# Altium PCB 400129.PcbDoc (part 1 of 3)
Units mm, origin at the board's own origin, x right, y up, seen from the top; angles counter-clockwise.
Board outline 295.85 x 54.86 mm, 2 copper layers (Top Layer, Bottom Layer), stack 1.671 mm thick; 222 components, 127 nets, 693 pads, 1827 vias.
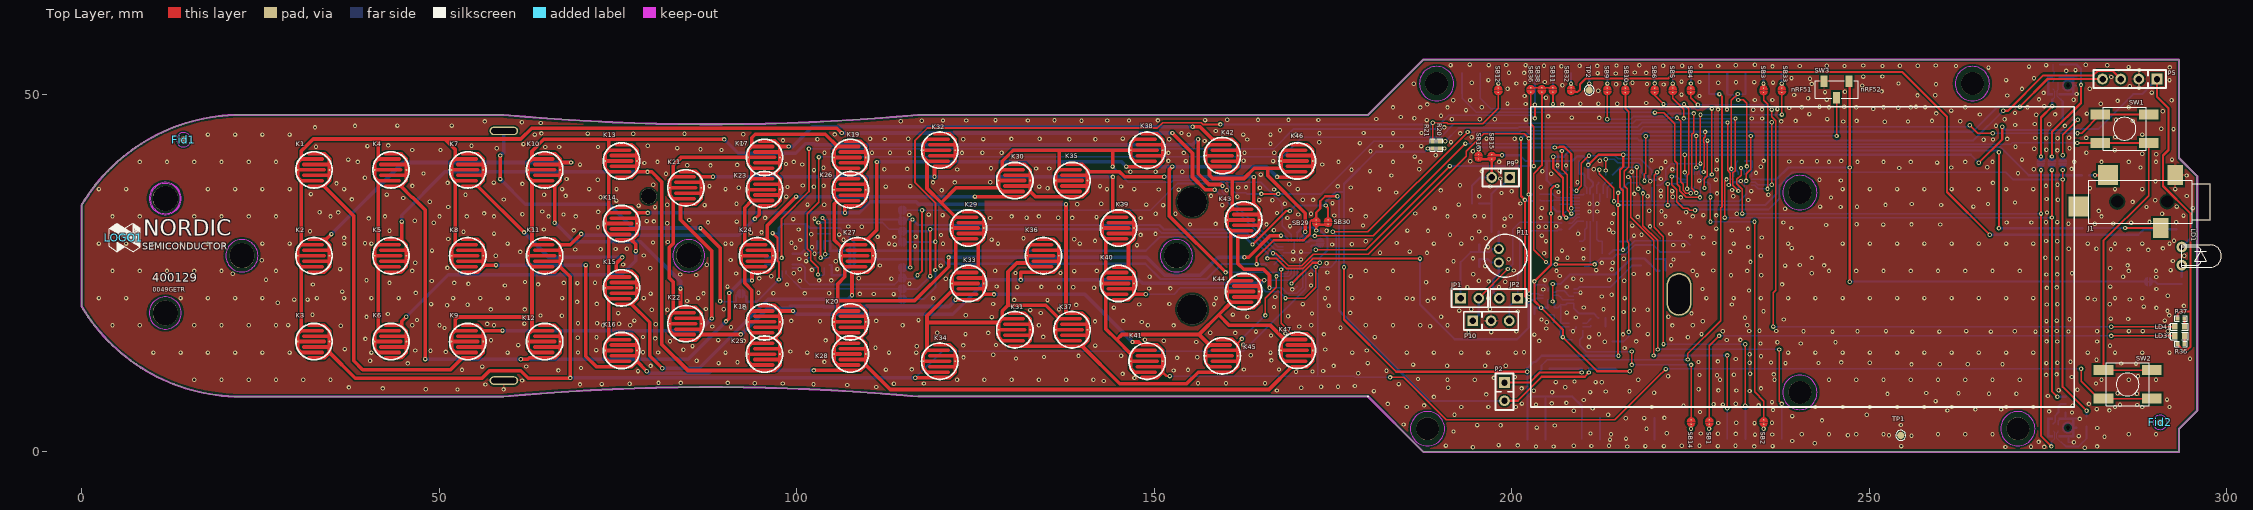
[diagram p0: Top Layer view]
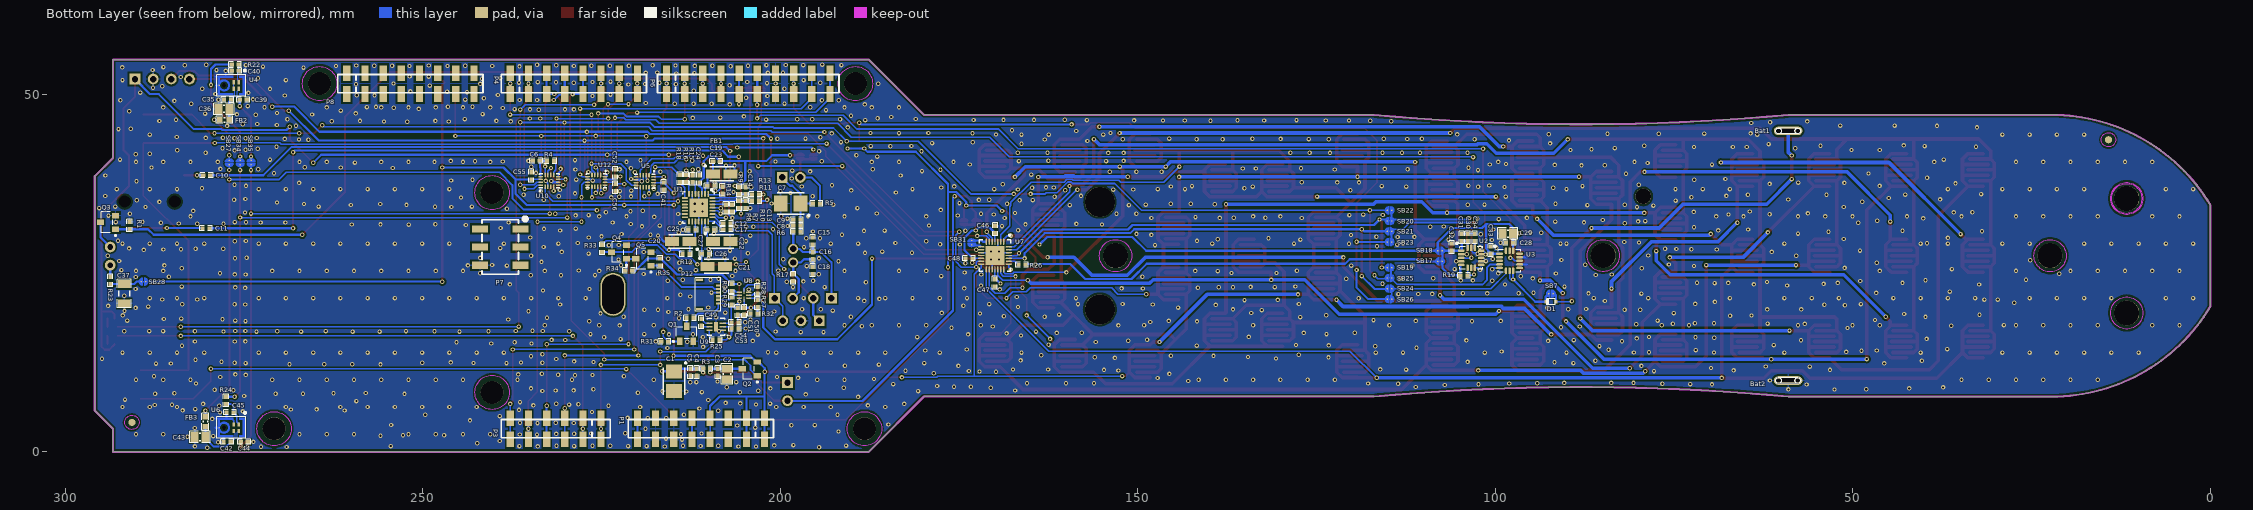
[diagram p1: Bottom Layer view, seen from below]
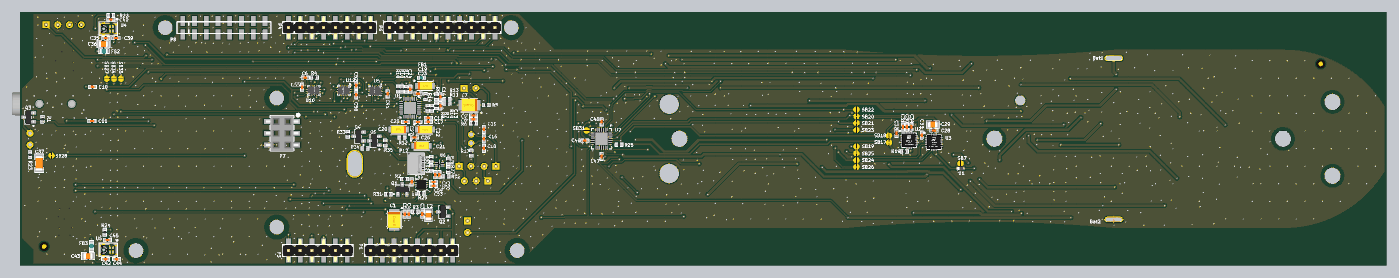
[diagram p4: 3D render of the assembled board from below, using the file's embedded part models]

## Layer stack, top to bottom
Top Solder: solder mask 0.0102, Solder Resist, Dk 3.5
Top Layer: signal copper 0.0356
Dielectric1: core 1.6, FR-4, Dk 4.8
Bottom Layer: signal copper 0.0356
Bottom Solder: solder mask 0.0102, Solder Resist, Dk 3.5

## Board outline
22.2,7.732 59,7.732 cw(c88,-308.964) 117,7.732 116.999,7.748 179.876,7.748 187.624,0 293.3,0 293.3,3.243 295.84,5.783 295.84,38.549 293.3,41.089 293.3,54.864 187.624,54.864 179.892,47.132 117,47.132 cw(c88,363.828) 59,47.132 22.2,47.132 ccw(c22.215,21.249) 0,34.532 0,20.332 -0.01,20.349 ccw(c22.2,33.589)

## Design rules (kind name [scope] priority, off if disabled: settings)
Clearance ANT_Clerance [InNet('ANT')] p1: gap=0.127
Clearance Polygon_Clearance [(InNamedPolygon('Top_Layer-GND')) or (InNamedPolygon('Bottom_Layer-GND'))] p2: gap=0.254
Clearance [All] p3: gap=0.127
ComponentClearance [All] p1 off: gap=0.254 collisioncheckmode=3 verticalgap=0.254 showdistances=FALSE
DiffPairsRouting [All] p1: maxlimit=0.15 minlimit=0.15 mostfreqgap=0.15 toplayer_minwidth=0.381 toplayer_maxwidth=0.381 toplayer_prefwidth=0.381 bottomlayer_minwidth=0.381 bottomlayer_maxwidth=0.381 bottomlayer_prefwidth=0.381 maxuncoupledlength=12.7
FabricationTestPointUsage TestPointUsage [All] p1: valid=0 allowmultiple=FALSE
FabricationTestpoint Testpoint [All] p1: side=3 testpointundercomponent=TRUE minsize=1.016 maxsize=2.54 preferedsize=1.524 minholesize=0 maxholesize=1.016 preferedholesize=0.813 testpointgrid=0.025 allowsidetop=TRUE allowsidebottom=TRUE usegrid=TRUE gridtolerance=0
Height [All] p1 off: minheight=0 maxheight=25.4 prefheight=12.7
HoleSize [All] p1: absolutevalues=TRUE maxlimit=6.35 minlimit=0.3 maxpercent=80.000 minpercent=20.000
MinimumAnnularRing [All] p1 off: minimumring=0.152
PolygonConnect PolygonConnect_1 [isVia and innet(gnd)] p1: connectstyle=Direct reliefconductorwidth=0.254 reliefentries=4 polygonreliefangle="90 Angle" airgapwidth=0.254
PolygonConnect [All] p2: connectstyle=Relief reliefconductorwidth=0.254 reliefentries=4 polygonreliefangle="90 Angle" airgapwidth=0.254
RoutingVias [All] p1: holewidth=0.305 width=0.61 viastyle="Through Hole" minholewidth=0.3 minwidth=0.6 maxholewidth=0.711 maxwidth=1.27
SilkToSolderMaskClearance SilkscreenOverComponentPads [IsPad] p1: minsilkscreentomaskgap=0.254 clearancetoexposedcopper=TRUE
SolderMaskExpansion [All] p1: expansion=0.076
Width [All] p1: maxlimit=2.54 minlimit=0.152 preferedwidth=0.152
23 further rules are at their usual default settings.

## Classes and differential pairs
component class "pca63519 - Power": Bat1 Bat2 C1 C2 C3 C4 C5 D1 P2 Q2 R3 SB7
component class "pca63519 - Codec": C7 C8 C9 C10 C11 C12 C13 C14 C15 C16 C17 C18 C19 C20 C21 C22 C23 C24 C25 C26 C27 FB1 J1 JP1 JP2 P9 P10 P11 R5 R6 R7 R8 R9 R10 R11 R12 R13 R14 R15 R16 R17 R18 SB15 SB16 U1
component class "pca63519 - Connectors": C6 C41 C52 C55 C56 Fid1 Fid2 LD3 LD4 LOGO1 P1 P3 P4 P5 P6 P7 P8 R4 R36 R37 SB1 SB2 SB3 SB4 SB5 SB6 SB9 SB10 SB11 SB12 SB14 SB32 SB33 SW3 TP1 TP2 U5 U10 U12
component class "pca63519 - Keyboard": C46 C47 C48 K1 K2 K3 K4 K5 K6 K7 K8 K9 K10 K11 K12 K13 K14 K15 K16 K17 K18 K19 K20 K21 K22 K23 K24 K25 K26 K27 K28 K29 K30 K31 K32 K33 K34 K35 K36 K37 K38 K39 K40 K41 K42 K43 K44 K45 K46 K47 R26 SB29 SB30 SB31 SB36 SW1 SW2 U7
component class "pca63519 - Sensors": C28 C29 C30 C31 C32 C33 C34 C35 C36 C37 C39 C40 C42 C43 C44 C45 FB2 FB3 LD1 Q3 R1 R19 R20 R21 R22 R23 R24 SB17 SB18 SB19 SB20 SB21 SB22 SB23 SB24 SB25 SB26 SB27 SB28 SB34 SB35 U2 U3 U4 U6
component class "pca63519 - TouchPad": C49 C50 C51 C53 C54 P12 Q1 Q4 Q5 R2 R25 R27 R28 R29 R30 R31 R32 R33 R34 R35 SB38 U8 U9

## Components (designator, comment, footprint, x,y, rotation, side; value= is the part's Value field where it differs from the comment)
Bat1 "AA" POLSATBATTERYHOLDER 59.05,44.882 r0 bottom
Bat2 "AA" POLSATBATTERYHOLDER 59.05,9.982 r0 bottom
C1 "100µF" CAPMP3528X21N 214.838,9.891 r270 bottom
C2 "22µF" CAPC2012X11L 207.438,10.887 r90 bottom
C3 "100nF" CAPC1005X04L 208.743,11.135 r90 bottom
C4 "100nF" CAPC1005X04L 211.693,11.131 r90 bottom
C5 "1.0µF" CAPC1005X04L 212.579,11.131 r90 bottom
C6 "33pF" CAPC1005X04L 234.098,40.695 r180 bottom
C7 "100µF" CAPMP3528X21N 198.541,34.726 r0 bottom
C8 "100nF" CAPC1005X04L 197.657,31.658 r180 bottom
C9 "1.0µF" CAPC1005X04L 197.657,32.493 r180 bottom
C10 "1.0µF" CAPC1005X04L 280.193,38.689 r180 bottom
C11 "1.0µF" CAPC1005X04L 280.286,31.281 r180 bottom
C12 "1.0µF" CAPC1005X04L 207.458,31.996 r0 bottom
C13 "N.C." CAPC1005X04L 204.832,34.589 r90 bottom
C14 "N.C." CAPC1005X04L 204.832,36.525 r270 bottom
C15 "10nF" CAPC1005X04L 195.452,29.486 r270 bottom
C16 "N.C." CAPC1005X04L 195.451,27.434 r90 bottom
C17 "1.0µF" CAPC1005X04L 207.458,31.121 r0 bottom
C18 "N.C." CAPC1005X04L 195.449,25.382 r90 bottom
C19 "10µF" CAPMP3216X18N 208.166,38.891 r180 bottom
C20 "10µF" CAPMP3216X18N 213.889,29.433 r0 bottom
C21 "10µF" CAPMP3216X18N 208.92,25.957 r180 bottom
C22 "10µF" CAPMP3216X18N 208.185,29.433 r180 bottom
C23 "100nF" CAPC1005X04L 209.687,37.234 r0 bottom
C24 "100nF" CAPC1005X04L 211.343,38.185 r270 bottom
C25 "100nF" CAPC1005X04L 212.353,31.083 r180 bottom
C26 "100nF" CAPC1005X04L 210.447,27.734 r0 bottom
C27 "100nF" CAPC1005X04L 209.712,31.083 r0 bottom
C28 "100nF" CAPC1005X04L 97.999,29.239 r180 bottom
C29 "10µF" CAPC2012X11L 98.246,30.529 r180 bottom
C30 "100nF" CAPC1005X04L 103.851,29.985 r270 bottom
C31 "2.2µF" CAPC1005X04L 104.697,29.983 r270 bottom
C32 "10nF" CAPC1005X04L 106.096,28.631 r270 bottom
C33 "100nF" CAPC1005X04L 100.623,28.219 r270 bottom
C34 "470nF" CAPC1005X04L 102.856,29.985 r270 bottom
C35 "10nF" CAPC1005X04L 277.278,49.264 r180 bottom
C36 "10µF" CAPC2012X11L 277.785,47.969 r180 bottom
C37 "100µF" CAPC3216X13L 291.719,22.134 r90 bottom
C39 "15pF" CAPC1005X04L 275.09,49.268 r0 bottom
C40 "15pF" CAPC1005X04L 276.201,53.285 r180 bottom
C41 "100nF" CAPC1005X04L 216.286,37.171 r90 bottom
C42 "10nF" CAPC1005X04L 277.338,1.388 r180 bottom
C43 "10µF" CAPC2012X11L 281.123,2.08 r180 bottom
C44 "15pF" CAPC1005X04L 274.949,1.388 r0 bottom
C45 "15pF" CAPC1005X04L 276.938,5.533 r180 bottom
C46 "100nF" CAPC1005X04L 169.953,31.112 r270 bottom
C47 "100nF" CAPC1005X04L 169.96,23.629 r90 bottom
C48 "100nF" CAPC1005X04L 173.583,27.064 r180 bottom
C49 "1.0µF" CAPC1005X04L 211.057,18.122 r270 bottom
C50 "100nF" CAPC1005X04L 205.052,19.663 r90 bottom
C51 "100nF" CAPC1005X04L 205.955,19.663 r90 bottom
C52 "10µF" CAPC1005X04L 223.065,39.005 r270 bottom
C53 "1.0µF" CAPC1005X04L 206.312,17.253 r0 bottom
C54 "4.7µF" CAPC1005X04L 206.312,18.101 r0 bottom
C55 "100nF" CAPC1005X04L 234.789,38.606 r270 bottom
C56 "100nF" CAPC1005X04L 223.065,36.981 r90 bottom
D1 "1PS79SB30.115" SOD-523 92.228,21.008 r180 bottom
FB1 "600R/0.3A" INDC1005X04L 208.921,40.658 r180 bottom
FB2 "600R/0.5A" INDC1608X06L 277.716,46.428 r0 bottom
FB3 "600R/0.5A" INDC1608X06L 280.373,4.235 r90 bottom
Fid1 "Fiducial mark" Fiducial 14.251,43.65 r0 top
Fid2 "Fiducial mark" Fiducial 290.642,4.128 r0 top
J1 "JACK, PHONO" SJ-3523-SMT-TR 291.655,34.996 r180 top
JP1 "Jumper" Jumper-2.54mm 194.105,21.502 r0 top
JP2 "Jumper" Jumper-2.54mm 199.516,21.494 r180 top
K1 "*" "PCB Switch"#1 32.5,39.432 r0 top
K2 "0" "PCB Switch"#1 32.5,27.432 r0 top
K3 "#" "PCB Switch"#1 32.5,15.432 r0 top
K4 "7" "PCB Switch"#1 43.25,39.432 r0 top
K5 "8" "PCB Switch"#1 43.25,27.432 r0 top
K6 "9" "PCB Switch"#1 43.25,15.432 r0 top
K7 "4" "PCB Switch"#1 54,39.432 r0 top
K8 "5" "PCB Switch"#1 54,27.432 r0 top
K9 "6" "PCB Switch"#1 54,15.432 r0 top
K10 "1" "PCB Switch"#2 64.75,39.432 r0 top
K11 "2" "PCB Switch"#1 64.75,27.432 r0 top
K12 "3" "PCB Switch"#1 64.75,15.432 r0 top
K13 "Red" "PCB Switch"#1 75.5,40.682 r0 top
K14 "Green" "PCB Switch"#1 75.5,31.932 r0 top
K15 "Yellow" "PCB Switch"#1 75.5,22.932 r0 top
K16 "Blue" "PCB Switch"#1 75.5,14.182 r0 top
K17 "PCB SW" "PCB Switch"#1 95.5,41.182 r0 top
K18 "PCB SW" "PCB Switch"#1 95.5,18.182 r0 top
K19 "PCB SW" "PCB Switch"#1 107.5,41.177 r0 top
K20 "PCB SW" "PCB Switch"#1 107.5,18.182 r0 top
K21 "TBD" "PCB Switch"#1 84.5,36.932 r0 top
K22 "TBD" "PCB Switch"#1 84.5,17.932 r0 top
K23 "V_Down" "PCB Switch"#1 95.5,36.682 r0 top
K24 "Mute" "PCB Switch"#1 94.5,27.432 r0 top
K25 "C_Down" "PCB Switch"#1 95.5,13.674 r0 top
K26 "V_Up" "PCB Switch"#1 107.5,36.663 r0 top
K27 "Back" "PCB Switch"#1 108.5,27.432 r0 top
K28 "C_Up" "PCB Switch"#1 107.5,13.682 r0 top
K29 "PCB SW" "PCB Switch"#1 124,31.307 r0 top
K30 "PCB SW" "PCB Switch"#1 130.5,37.944 r0 top
K31 "PCB SW" "PCB Switch"#3 130.5,17.083 r0 top
K32 "Menu" "PCB Switch"#1 120,42.193 r0 top
K33 "Down" "PCB Switch"#1 124,23.557 r0 top
K34 "Exit" "PCB Switch"#1 120,12.682 r0 top
K35 "Left" "PCB Switch"#1 138.5,37.944 r0 top
K36 "OK" "PCB Switch"#1 134.5,27.432 r0 top
K37 "Right" "PCB Switch"#1 138.5,17.083 r0 top
K38 "TBD" "PCB Switch"#1 149,42.182 r0 top
K39 "PCB SW" "PCB Switch"#1 145,31.307 r0 top
K40 "Up" "PCB Switch"#4 145,23.557 r0 top
K41 "TBD" "PCB Switch"#1 149,12.682 r0 top
K42 "TV" "PCB Switch"#1 159.5,41.432 r0 top
K43 "SAT" "PCB Switch"#1 162.5,32.432 r0 top
K44 "DVD" "PCB Switch"#1 162.5,22.432 r0 top
K45 "AUX" "PCB Switch"#1 159.5,13.432 r0 top
K46 "Power" "PCB Switch"#1 170,40.682 r0 top
K47 "TBD" "PCB Switch"#1 170,14.194 r0 top
LD1 "IR333C/H2" LED_3MM_SIDE 293.691,27.391 r0 top
LD3 "L0603G" LED_0603_G 293.37,16.219 r0 top
LD4 "L0603G" LED_0603_G 293.37,17.503 r0 top
LOGO1 "Nordic Logo M" NORDIC_LOGO_M 5.86,29.941 r0 top
P1 "Pin List 1x8" LIST_1x8_SMD 202.18,3.243 r0 bottom
P2 "Pin List 1x2" LIST_1x2 198.972,8.421 r270 top
P3 "Pin List 1x6" LIST_1x6_SMD 225.04,3.243 r0 bottom
P4 "Pin List 1x8" LIST_1x8_SMD 237.74,51.503 r180 bottom
P5 "Pin List 1x4" LIST_1x4 286.413,52.14 r180 top
P6 "Pin List 1x10" LIST_1x10_SMD 215.896,51.503 r180 bottom
P7 "Socket 2x3" SOCKET_2x3_SMD-2.54mm-bottom 239.137,28.643 r270 top
P8 "Pin List 1x8" LIST_1x8_SMD 260.6,51.503 r180 bottom
P9 "Pin List 1x2" LIST_1x2 198.452,38.381 r180 top
P10 "Pin List 1x3" LIST_1x3 197.091,18.321 r0 top
P11 "VMOB6027D" MIC_VMOB6027D 199.129,27.432 r0 top
P12 "5034800600" "Molex 5034800600" 210.073,22.025 r270 bottom
Q1 "FDV303N" SOT-23a 214.034,15.457 r180 bottom
Q2 "FDV304P" SOT-23a 203.194,10.674 r90 bottom
Q3 "FDV303N" SOT-23a 292.949,31.148 r90 bottom
Q4 "BC847C" SOT-23a 221.492,26.995 r90 bottom
Q5 "BC847C" SOT-23a 218.076,26.046 r90 bottom
R1 "1M0" RESC1005X04L 291.007,31.664 r270 bottom
R2 "220R" RESC1005X04L 212.6,18.707 r180 bottom
R3 "10R" RESC1005X04L 210.273,11.633 r0 bottom
R4 "33R" RESC1005X04L 232.117,40.695 r0 bottom
R5 "0R" RESC1005X04L 194.939,34.74 r180 bottom
R6 "2k2" RESC1005X04L 197.661,30.789 r180 bottom
R7 "N.C." RESC1005X04L 206.709,34.079 r270 bottom
R8 "0R" RESC1005X04L 207.577,34.079 r90 bottom
R9 "4k3" RESC1005X04L 205.725,36.525 r90 bottom
R10 "4k3" RESC1005X04L 205.725,34.59 r270 bottom
R11 "0R" RESC1005X04L 203.425,35.089 r0 bottom
R12 "10R" RESC1005X04L 213.159,27.691 r0 bottom
R13 "0R" RESC1005X04L 203.425,36.025 r0 bottom
R14 "33R" RESC1005X04L 208.066,36.591 r270 bottom
R15 "1k" RESC1005X04L 212.241,38.191 r90 bottom
R16 "33R" RESC1005X04L 213.138,38.208 r270 bottom
R17 "0R" RESC1005X04L 198.178,24.348 r90 bottom
R18 "33R" RESC1005X04L 214.023,38.214 r270 bottom
R19 "N.C." RESC1005X04L 104.39,24.693 r0 bottom
R20 "10k" RESC1005X04L 189.949,42.935 r270 top
R21 "10k" RESC1005X04L 188.943,42.935 r270 top
R22 "100R" RESC1005X04L 276.201,54.174 r180 bottom
R23 "2R2" RESC1005X04L 293.674,23.992 r270 bottom
R24 "100R" RESC1005X04L 277.507,7.21 r270 bottom
R25 "1M0" RESC1005X04L 208.967,15.664 r180 bottom
R26 "100k" RESC1005X04L 166.181,26.169 r180 bottom
R27 "N.C." RESC1005X04L 203.156,20.741 r90 bottom
R28 "N.C." RESC1005X04L 203.156,22.61 r270 bottom
R29 "4k7" RESC1005X04L 206.827,21.096 r90 bottom
R30 "4k7" RESC1005X04L 206.829,23.001 r270 bottom
R31 "1M0" RESC1005X04L 216.146,15.439 r180 bottom
R32 "N.C." RESC1005X04L 203.649,19.316 r0 bottom
R33 "N.C." RESC1005X04L 224.886,28.451 r270 bottom
R34 "N.C." RESC1005X04L 221.167,25.344 r0 bottom
R35 "N.C." RESC1005X04L 216.798,26.554 r270 bottom
R36 "820R" RESC1005X04L 293.573,15.088 r180 top
R37 "820R" RESC1005X04L 293.573,18.669 r180 top
SB1 "Solderbridge" Solderbridge_SHORTED_0.4 227.622,4.477 r270 top net-tie
SB2 "Solderbridge" Solderbridge_SHORTED_0.4 235.211,4.477 r270 top net-tie
SB3 "Solderbridge" Solderbridge_SHORTED_0.4 235.196,50.257 r90 top net-tie
SB4 "Solderbridge" Solderbridge_SHORTED_0.4 225.044,50.252 r90 top net-tie
SB5 "Solderbridge" Solderbridge_SHORTED_0.4 222.5,50.259 r90 top net-tie
SB6 "Solderbridge" Solderbridge_0.4#1 219.96,50.252 r90 top
SB7 "Solderbridge" Solderbridge_0.4#1 92.528,22.134 r180 bottom
SB9 "Solderbridge" Solderbridge_SHORTED_0.4 213.346,50.252 r90 top net-tie
SB10 "Solderbridge" Solderbridge_SHORTED_0.4 215.885,50.252 r90 top net-tie
SB11 "Solderbridge" Solderbridge_0.4#1 205.741,50.93 r270 top
SB12 "Solderbridge" Solderbridge_SHORTED_0.4 198.102,50.254 r90 top net-tie
SB14 "Solderbridge" Solderbridge_SHORTED_0.4 225.081,4.477 r270 top net-tie
SB15 "Solderbridge" Solderbridge_0.4#1 197.195,41.577 r270 top
SB16 "Solderbridge" Solderbridge_SHORTED_0.4 195.34,41.588 r270 top net-tie
SB17 "Solderbridge" Solderbridge_SHORTED_0.4 108.042,26.641 r180 bottom net-tie
SB18 "Solderbridge" Solderbridge_0.4#1 108.042,28.131 r180 bottom
SB19 "Solderbridge" Solderbridge_0.4#2 114.463,25.775 r0 bottom
SB20 "Solderbridge" Solderbridge_SHORTED_0.4 114.463,32.289 r0 bottom net-tie
SB21 "Solderbridge" Solderbridge_SHORTED_0.4 114.463,30.846 r0 bottom net-tie
SB22 "Solderbridge" Solderbridge_0.4#1 115.082,33.781 r180 bottom
SB23 "Solderbridge" Solderbridge_0.4#2 115.082,29.347 r180 bottom
SB24 "Solderbridge" Solderbridge_0.4#3 114.463,22.823 r0 bottom
SB25 "Solderbridge" Solderbridge_SHORTED_0.4 114.463,24.319 r0 bottom net-tie
SB26 "Solderbridge" Solderbridge_SHORTED_0.4 114.463,21.366 r0 bottom net-tie
SB27 "Solderbridge" Solderbridge_0.4#1 277.041,40.142 r90 bottom
SB28 "Solderbridge" Solderbridge_SHORTED_0.4 288.72,23.819 r0 bottom net-tie
SB29 "Solderbridge" Solderbridge_SHORTED_0.4 172.655,32.432 r270 top net-tie
SB30 "Solderbridge" Solderbridge_0.4#2 174.297,32.435 r270 top
SB31 "Solderbridge" Solderbridge_0.4#2 173.187,28.939 r90 bottom
SB32 "Solderbridge" Solderbridge_SHORTED_0.4 208.28,50.308 r90 top net-tie
SB33 "Solderbridge" Solderbridge_SHORTED_0.4 237.768,50.257 r90 top net-tie
SB34 "Solderbridge" Solderbridge_0.4#1 275.514,40.762 r270 bottom
SB35 "Solderbridge" Solderbridge_0.4#1 273.988,40.762 r270 bottom
SB36 "Solderbridge" Solderbridge_0.4#1 202.648,50.93 r270 top
SB38 "Solderbridge" Solderbridge_0.4#1 204.203,50.31 r90 top
SW1 "MB Left" ALPS_SKHUxxx010_WO_GND 285.681,45.193 r180 top
SW2 "MB Right" ALPS_SKHUxxx010_WO_GND 286.104,9.435 r0 top
SW3 "Switch" CJS-120xA 245.415,50.673 r180 top
TP1 "Ø1.0mm,SMD" TP_SMD_Ø1.0mm 254.381,2.311 r0 top
TP2 "Ø1.0mm,SMD" TP_SMD_Ø1.0mm 210.816,50.579 r0 top
U1 "ES8218" QFN45P400X400X90_HS-29N 211.4,34.159 r270 bottom
U2 "ICM-20608" PQFN50P300X300X100-16N 103.356,27.141 r180 bottom
U3 "LIS3DH" PQFN50P300X300X100-16N 97.999,26.721 r180 bottom
U4 "MP34DB01" "RHLGA-4 (3x4x1mm)" 277.76,51.253 r0 bottom
U5 "NX3DV2567" XQFN40P180X260X50-16N 218.936,37.855 r270 bottom
U6 "MP34DB01" "RHLGA-4 (3x4x1mm)" 277.763,3.386 r0 bottom
U7 "SX1509BIULTRT" QFN40P400X400X60_HS-29N 169.957,27.461 r270 bottom
U8 "FXMA2102" QFN40P140X120X55-8N 205.052,21.916 r0 bottom
U9 "LTC3240EDC-3.3" SON50P200X80_HS-7N 208.967,17.503 r0 bottom
U10 "NX3DV2567" XQFN40P180X260X50-16N 232.274,37.905 r90 bottom
U12 "NX3DV2567" XQFN40P180X260X50-16N 225.716,37.905 r270 bottom

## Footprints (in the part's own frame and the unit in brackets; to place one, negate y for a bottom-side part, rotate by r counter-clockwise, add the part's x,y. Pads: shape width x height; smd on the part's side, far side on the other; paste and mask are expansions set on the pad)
ALPS_SKHUxxx010_WO_GND [mm] "6.2×6.5mm TACT Switch, without ground connector"
  rect 2.75x1.4 smd: 1(-3.375,2) 1(3.375,2) 2(-3.375,-2) 2(3.375,-2)
  silkscreen extent -3,-3 3,3, body extent -4,-3 4,3.3, height 3.1
CAPC1005X04L [mm] "Chip Capacitor, 2-Leads, Body 1.0x0.5mm, IPC High Density"
  rect 0.6x0.5 smd: 1(-0.5,0) 2(0.5,0)
  silkscreen extent -0.9,-0.35 0.9,0.35, body extent -0.51,-0.25 0.51,0.25, height 0.5
CAPC2012X11L [mm] "Chip Capacitor, 2-Leads, Body 2.0x1.3mm, IPC High Density"
  rect 1.1x1.4 smd: 1(-0.75,0) 2(0.75,0)
  silkscreen extent -1.43,-0.8 1.42,0.8, body extent -1,-0.62 1,0.63, height 0.77
CAPC3216X13L [mm] "Chip Capacitor, 2-Leads, Body 3.2x1.6mm, IPC High Density"
  rect 1.1x1.75 smd: 1(-1.35,0) 2(1.35,0)
  silkscreen extent -2,-0.97 2,0.97, body extent -1.6,-0.8 1.6,0.8, height 0.99
CAPMP3216X18N [mm] "Molded Capacitor, 2-Leads, Body 3.20x1.60mm, IPC Medium Density"
  rect 1.95x1.25 smd: 1(-1.225,0) 2(1.225,0)
  silkscreen extent -2.43,-0.95 1.7,1.22, body extent -1.7,-0.8 1.7,0.8, height 1.64
CAPMP3528X21N [mm] "Molded Capacitor, 2-Leads, Body 3.5x2.8mm, IPC Medium Density"
  rect 1.95x2.25 smd: 1(-1.375,0) 2(1.375,0)
  silkscreen extent -2.67,-1.5 1.9,1.77, body extent -1.84,-1.41 1.85,1.41, height 2.09
CJS-120xA [mm] "Slide Switches - SPDT, SMD, ON-ON"
  rect 1x1.6 smd: 1(1.75,-1.15) 2(0,1.15) 3(-1.75,-1.15)
  silkscreen extent -3,-1.25 3,1.25, body extent -3,-1.4 3,1.45, height 2.5
Fiducial [mm] "Fiducial Mark"
  round 1 smd paste-10 mask+0.5: 0(0,0)
  round 1 smd far side paste-10 mask+0.5: 0(0,0)
  Keep-Out Layer circle w0.01: c0,0 r1
INDC1005X04L [mm] "Chip Inductor, 2-Leads, Body 1.0x0.5mm, IPC High Density"
  rect 0.65x0.5 smd: 1(-0.475,0) 2(0.475,0)
  silkscreen extent -0.9,-0.35 0.9,0.35, body extent -0.5,-0.3 0.5,0.3, height 0.5
INDC1608X06L [mm] "Chip Inductor, 2-Leads, Body 1.6x0.8mm, IPC High Density"
  rect 0.75x0.8 smd: 1(-0.675,0) 2(0.675,0)
  silkscreen extent -1.17,-0.5 1.17,0.5, body extent -0.8,-0.48 0.8,0.47, height 0.8
Jumper-2.54mm [mm] "Straight 2.54mm through-hole mounted jumper"
  rect 1.5x1.5 hole 0.9: 1(-1.27,0)
  round 1.5 hole 0.9: 2(1.27,0)
  silkscreen extent -2.54,-1.27 2.54,1.27, body extent -2.54,-1.27 2.44,1.23, height 8.2
LED_3MM_SIDE [mm] "Typical 3mm LED; 2 Leads"
  round 1.5 hole 0.8: 1(0,1.27) 2(0,-1.27)
  silkscreen extent 0,-1.55 5.55,1.55
LED_0603_G [mil] "SMD Super Bright LED, GREEN"
  rect 30x32 smd: 1(-27.5,0) 2(27.5,0)
  silkscreen extent -58,-20 48,20, body extent -32,-16 32,16, height 24
LIST_1x2 [mm] "Pin List, 2.54mm through hole"
  rect 1.5x1.5 hole 0.9: 1(-1.27,0)
  round 1.5 hole 0.9: 2(1.27,0)
  silkscreen extent -2.54,-1.27 2.54,1.27, body extent -2.54,-1.27 2.44,1.23, height 8.2
LIST_1x3 [mm] "Pin List, 2.54mm through hole"
  rect 1.5x1.5 hole 0.9: 1(-2.54,0)
  round 1.5 hole 0.9: 2(0,0) 3(2.54,0)
  silkscreen extent -3.81,-1.27 3.81,1.27, body extent -3.81,-1.27 3.71,1.23, height 8.2
LIST_1x4 [mm] "Pin List, 2.54mm through hole"
  rect 1.5x1.5 hole 0.9: 1(-3.81,0)
  round 1.5 hole 0.9: 2(-1.27,0) 3(1.27,0) 4(3.81,0)
  silkscreen extent -5.08,-1.27 5.08,1.27, body extent -5.18,-1.25 4.98,1.25, height 8.2
LIST_1x6_SMD [mm] "Pin List, 2.54mm, SMD"
  rect 1.02x2.19 smd: 1(0,-1.465) 1(0,1.465) 2(2.54,-1.465) 2(2.54,1.465) 3(5.08,-1.465) 3(5.08,1.465) 4(7.62,-1.465) 4(7.62,1.465) 5(10.16,-1.465) 5(10.16,1.465) 6(12.7,-1.465) 6(12.7,1.465)
  silkscreen extent -1.27,-1.27 13.97,1.27, body extent -1.27,-2.5 13.97,2.5, height 9.82
LIST_1x8_SMD [mm] "Pin List, 2.54mm, SMD"
  rect 1.02x2.19 smd: 1(0,-1.465) 1(0,1.465) 2(2.54,-1.465) 2(2.54,1.465) 3(5.08,-1.465) 3(5.08,1.465) 4(7.62,-1.465) 4(7.62,1.465) 5(10.16,-1.465) 5(10.16,1.465) 6(12.7,-1.465) 6(12.7,1.465) 7(15.24,-1.465) 7(15.24,1.465) 8(17.78,-1.465) 8(17.78,1.465)
  silkscreen extent -1.27,-1.27 19.05,1.27, body extent -1.27,-2.5 19.05,2.5, height 9.82
LIST_1x10_SMD [mm] "Pin List, 2.54mm, SMD"
  rect 1.02x2.19 smd: 1(0,-1.465) 1(0,1.465) 2(2.54,-1.465) 2(2.54,1.465) 3(5.08,-1.465) 3(5.08,1.465) 4(7.62,-1.465) 4(7.62,1.465) 5(10.16,-1.465) 5(10.16,1.465) 6(12.7,-1.465) 6(12.7,1.465) 7(15.24,-1.465) 7(15.24,1.465) 8(17.78,-1.465) 8(17.78,1.465) 9(20.32,-1.465) 9(20.32,1.465) 10(22.86,-1.465) 10(22.86,1.465)
  silkscreen extent -1.27,-1.27 24.13,1.27, body extent -1.27,-2.5 24.13,2.5, height 9.82
MIC_VMOB6027D [mm]
  round 1.4 hole 0.9: 1(-0.95,0.95) 2(-0.95,-0.95)
  silkscreen extent -3,-3 3,3, body extent -3,-3 3,3, height 5
"Molex 5034800600" [mm] "CONN FFC FPC 6POS 0.50MM R/A"
  rect 0.3x0.7 smd: 1(-1.25,1.425) 2(-0.75,1.425) 3(-0.25,1.425) 4(0.25,1.425) 5(0.75,1.425) 6(1.25,1.425)
  rect 0.3x1 smd: 7(-2.04,-1.225) 7(2.04,-1.225)
  silkscreen extent -2.35,-1.8 2.35,1.8, body extent -2.35,-1.8 2.35,1.8, height 1.88
NORDIC_LOGO_M [mm] "Medium Nordic Logo"
  silkscreen extent -2.03,-1.98 2.28,2.02
"PCB Switch"#1 [mil]
  round 10 smd: 1(-90,0) 2(85,0)
  Top Layer lines w20: -55,-30 75,-30 ; -55,30 75,30 ; -30,-90 55,-90 85,-60 85,-30 ; -30,90 8.49,90 10.05,90 20.68,90 55,90 60.25,84.75 85,60 ; 45,-60 -41.92,-60 -70,-60 -90,-40 -90,0 ; 45,60 -69.3,60 -70,60 -90,40 -90,0 ; 55,0 -90,0 ; 85,-30 85,-9.84 ; 85,-30 85,-20 ; 85,-30 85,-20 ; 85,-20 85,-9.84 ; 85,-20 85,-9.84 ; 85,-9.84 85,0 ; 85,-9.84 85,0 ; 85,-9.84 85,0 ; 85,0 85,25.46 ; 85,0 85,20 ; 85,0 85,20 ; 85,20 85,25.46 ; 85,20 85,25.46 ; 85,25.46 85,60 ; 85,25.46 85,60 ; 85,25.46 85,60
  silkscreen extent -100,-100 100,100
"PCB Switch"#2 [mil]
  round 10 smd: 1(-90,0) 2(85,0)
  Top Layer lines w20: -55,-30 75,-30 ; -55,30 75,30 ; -30,-90 55,-90 85,-60 85,-30 ; -30,90 8.49,90 10.05,90 20.68,90 55,90 60.25,84.75 85,60 ; 45,-60 -41.92,-60 -70,-60 -90,-40 -90,0 ; 45,60 -69.3,60 -70,60 -90,40 -90,0 ; 55,0 -90,0 ; 85,-30 85,-9.84 ; 85,-30 85,-20 ; 85,-30 85,-20 ; 85,-20 85,-9.84 ; 85,-20 85,-9.84 ; 85,-9.84 85,0 ; 85,-9.84 85,0 ; 85,-9.84 85,0 ; 85,0 85,25.46 ; 85,0 85,20 ; 85,0 85,20 ; 85,20 85,25.46 ; 85,20 85,25.46 ; 85,25.46 85,42.73 ; 85,25.46 85,42.73 ; 85,25.46 85,42.73 ; 85,42.73 85,60 ; 85,42.73 85,42.73 ; 85,42.73 85,60 ; 85,42.73 85,60
  silkscreen extent -100,-100 100,100
"PCB Switch"#3 [mil]
  round 10 smd: 1(-90,0) 2(85,0)
  Top Layer lines w20: -55,-30 75,-30 ; -55,30 75,30 ; -30,-90 55,-90 ; -30,90 8.49,90 10.05,90 20.68,90 55,90 60.25,84.75 85,60 ; 45,-60 -41.92,-60 -70,-60 -90,-40 -90,0 ; 45,60 -69.3,60 -70,60 -90,40 -90,0 ; 55,0 -90,0 ; 55,-90 85,-60 85,-30 ; 55,-90 55,-90 ; 85,-30 85,-9.84 ; 85,-30 85,-20 ; 85,-30 85,-20 ; 85,-20 85,-9.84 ; 85,-20 85,-9.84 ; 85,-9.84 85,0 ; 85,-9.84 85,0 ; 85,-9.84 85,0 ; 85,0 85,25.46 ; 85,0 85,20 ; 85,0 85,20 ; 85,20 85,25.46 ; 85,20 85,25.46 ; 85,25.46 85,60 ; 85,25.46 85,60 ; 85,25.46 85,60
  silkscreen extent -100,-100 100,100
"PCB Switch"#4 [mil]
  round 10 smd: 1(-90,0) 2(85,0)
  Top Layer lines w20: -70,60 -69.3,60 45,60 ; -55,-30 75,-30 ; -55,30 75,30 ; -30,-90 55,-90 85,-60 85,-30 ; -30,90 8.49,90 10.05,90 20.68,90 55,90 60.25,84.75 85,60 ; 45,-60 -41.92,-60 -70,-60 -90,-40 -90,0 55,0 ; 85,-30 85,-9.84 ; 85,-30 85,-20 ; 85,-30 85,-20 ; 85,-20 85,-9.84 ; 85,-20 85,-9.84 ; 85,-9.84 85,0 ; 85,-9.84 85,0 ; 85,-9.84 85,0 ; 85,0 85,25.46 ; 85,0 85,20 ; 85,0 85,20 ; 85,20 85,25.46 ; 85,20 85,25.46 ; 85,25.46 85,60 ; 85,25.46 85,60 ; 85,25.46 85,60
  silkscreen extent -100,-100 100,100
POLSATBATTERYHOLDER [mm] "SOT23, 5-Leads, Body 2,90x2,80mm, Pitch 0,95mm, IPC Medium Density"
  oval 4x1.2 hole 0.8 slot 3.5 at 0 deg: 1(0,0)
PQFN50P300X300X100-16N [mm] "PQFN, 16-Leads, Body 3.00x3.00mm, Pitch 0.50mm, IPC Medium Density"
  oval 0.95x0.35 smd: 1(-1.4,1) 2(-1.4,0.5) 3(-1.4,0) 4(-1.4,-0.5) 5(-1.4,-1) 9(1.4,-1) 10(1.4,-0.5) 11(1.4,0) 12(1.4,0.5) 13(1.4,1)
  oval 0.35x0.95 smd: 6(-0.5,-1.4) 7(0,-1.4) 8(0.5,-1.4) 14(0.5,1.4) 15(0,1.4) 16(-0.5,1.4)
  silkscreen extent -2.15,-1.58 1.58,2.15, body extent -1.5,-1.5 1.5,1.5, height 1.01
QFN40P140X120X55-8N [mm] "QFN, 8-Leads, Body 1,40x1,20mm, Pitch 0,40mm, IPC Medium Density"
  oval 0.2x0.75 smd: 1(0,0.55) 5(0,-0.55)
  oval 0.75x0.2 smd: 2(-0.65,0.4) 3(-0.65,0) 4(-0.65,-0.4) 6(0.65,-0.4) 7(0.65,0) 8(0.65,0.4)
  silkscreen extent -0.05,1.28 0.05,1.37, body extent -0.73,-0.63 0.72,0.63, height 0.55
QFN40P400X400X60_HS-29N [mm] "QFN, 28-Leads, Body 4,00x4,00mm, Pitch 0,40mm, Thermal Pad 2,65x2,65mm, IPC Medium Density"
  oval 0.85x0.2 smd: 1(-1.925,1.2) 2(-1.925,0.8) 3(-1.925,0.4) 4(-1.925,0) 5(-1.925,-0.4) 6(-1.925,-0.8) 7(-1.925,-1.2) 15(1.925,-1.2) 16(1.925,-0.8) 17(1.925,-0.4) 18(1.925,0) 19(1.925,0.4) 20(1.925,0.8) 21(1.925,1.2)
  oval 0.2x0.85 smd: 8(-1.2,-1.925) 9(-0.8,-1.925) 10(-0.4,-1.925) 11(0,-1.925) 12(0.4,-1.925) 13(0.8,-1.925) 14(1.2,-1.925) 22(1.2,1.925) 23(0.8,1.925) 24(0.4,1.925) 25(0,1.925) 26(-0.4,1.925) 27(-0.8,1.925) 28(-1.2,1.925)
  rect 2.65x2.65 smd: 29(0,0)
  silkscreen extent -2.97,-2.2 2.2,2.2, body extent -2.05,-2.05 2.05,2.05, height 0.6
QFN45P400X400X90_HS-29N [mm] "QFN, 28-Leads, Body 4,00x4,00mm, Pitch 0,45mm, Thermal Pad 2,60x2,60mm, IPC Medium Density"
  oval 0.85x0.25 smd: 1(-1.925,1.35) 2(-1.925,0.9) 3(-1.925,0.45) 4(-1.925,0) 5(-1.925,-0.45) 6(-1.925,-0.9) 7(-1.925,-1.35) 15(1.925,-1.35) 16(1.925,-0.9) 17(1.925,-0.45) 18(1.925,0) 19(1.925,0.45) 20(1.925,0.9) 21(1.925,1.35)
  oval 0.25x0.85 smd: 8(-1.35,-1.925) 9(-0.9,-1.925) 10(-0.45,-1.925) 11(0,-1.925) 12(0.45,-1.925) 13(0.9,-1.925) 14(1.35,-1.925) 22(1.35,1.925) 23(0.9,1.925) 24(0.45,1.925) 25(0,1.925) 26(-0.45,1.925) 27(-0.9,1.925) 28(-1.35,1.925)
  rect 2.6x2.6 smd: 29(0,0)
  silkscreen extent -2.62,-2.19 2.19,2.19, body extent -2.04,-2.04 2.04,2.04, height 0.9
RESC1005X04L [mm] "Chip Resistor, 2-Leads, Body 1.0x0.5mm, IPC High Density"
  rect 0.6x0.55 smd: 1(-0.5,0) 2(0.5,0)
  silkscreen extent -0.87,-0.38 0.88,0.38, body extent -0.5,-0.25 0.5,0.25, height 0.3
"RHLGA-4 (3x4x1mm)" [mm] "RHLGA-4 Package, 3mm x 4mm x 1mm"
  round 0.3 hole 0.6 unplated: 0(0,0)
  rect 0.4x0.6 smd paste-8 mask+0.076: 1(-2.05,-0.45) 2(-1.35,-0.45) 3(-1.35,0.45) 4(-2.05,0.45)
  round 0.2 smd paste-8 mask+0.076: 5(0.7,0)
  Top Layer circle w0.3: c0,0 r0.7
  Top Layer region: -2.9,1.4 -2.55,1.4 -2.55,-1.4 -2.9,-1.4
  Top Layer region: 0.55,1.4 0.9,1.4 0.9,-1.4 0.55,-1.4
  Top Layer region: 0.55,-1.4 -1.3,-1.4 -1.3,-1.05 0.55,-1.05
  Top Layer region: -2.1,-1.4 -2.55,-1.4 -2.55,-1.05 -2.1,-1.05
  Top Layer region: -2.1,1.05 -2.55,1.05 -2.55,1.4 -2.1,1.4
  Top Layer region: 0.55,1.05 -1.3,1.05 -1.3,1.4 0.55,1.4
  silkscreen extent -3.06,-2.21 1,1.5, body extent -3,-1.5 1,1.5, height 1
SJ-3523-SMT-TR [mm] "Jack 3.5mm"
  rect 2.2x2.8 smd: 1(-1.1,-3.7) 3(0.9,3.7)
  rect 2.8x2.8 smd: 2(8.3,-3.7) 4(12.4,0.65)
  round 1 hole 1.7 unplated: ""(0,0) ""(7,0)
  silkscreen extent -6,-3 11,3, body extent -5.96,-4.5 11.04,4.5, height 5
SOCKET_2x3_SMD-2.54mm-bottom [mm] "Socket, 2.54mm, SMD"
  rect 1.02x2.22 smd far side: 1(-2.54,-2.825) 2(-2.54,2.825) 3(0,-2.825) 4(0,2.825) 5(2.54,-2.825) 6(2.54,2.825)
  body extent -3.81,-3.52 3.81,3.52, height 7.47
SOD-523 [mm]
  rect 0.4x0.5 smd: 1(0.7,0) 3(-0.7,0)
  silkscreen extent -0.6,-0.4 0.6,0.4, body extent -0.8,-0.4 0.8,0.4, height 0.7
Solderbridge_0.4#1 [mm]
  round 0.2 smd paste-10: 1(0,0) 2(0.625,0)
  Top Layer region: 0.236,-0.553 0.183,-0.605 0.107,-0.554 -0.097,-0.351 -0.15,-0.292 -0.208,-0.193 -0.236,-0.099 -0.231,0.122 -0.206,0.193 -0.122,0.33 -0.038,0.411 0.054,0.469 0.153,0.556 0.233,0.565
  Top Layer region: 0.389,0.553 0.516,0.512 0.648,0.424 0.721,0.351 0.775,0.292 0.833,0.193 0.861,0.099 0.856,-0.122 0.831,-0.193 0.747,-0.33 0.663,-0.411 0.464,-0.536 0.389,-0.559
  Top Layer lines w0.152: 0.156,0.557 ccw(c0.277,0) 0.16,-0.558 ; 0.466,0.557 cw(c0.343,0) 0.465,-0.557
Solderbridge_0.4#2 [mm]
  round 0.2 smd paste-10: 1(0,0) 2(0.625,0)
  Top Layer region: 0.236,-0.553 0.183,-0.605 0.107,-0.554 -0.097,-0.351 -0.15,-0.292 -0.208,-0.193 -0.236,-0.099 -0.231,0.122 -0.206,0.193 -0.122,0.33 -0.038,0.411 0.054,0.469 0.153,0.556 0.233,0.565
  Top Layer region: 0.389,0.553 0.516,0.512 0.648,0.424 0.721,0.351 0.775,0.292 0.833,0.193 0.861,0.099 0.856,-0.122 0.831,-0.193 0.747,-0.33 0.663,-0.411 0.464,-0.536 0.389,-0.559
  Top Layer lines w0.152: 0.156,0.557 ccw(c0.277,0) 0.16,-0.558 ; 0.465,-0.557 ccw(c0.343,0) 0.913,0 ccw(c0.343,0) 0.466,0.557
Solderbridge_0.4#3 [mm]
  round 0.2 smd paste-10: 1(0,0) 2(0.625,0)
  Top Layer region: 0.236,-0.553 0.183,-0.605 0.107,-0.554 -0.097,-0.351 -0.15,-0.292 -0.208,-0.193 -0.236,-0.099 -0.231,0.122 -0.206,0.193 -0.122,0.33 -0.038,0.411 0.054,0.469 0.153,0.556 0.233,0.565
  Top Layer region: 0.389,0.553 0.516,0.512 0.648,0.424 0.721,0.351 0.775,0.292 0.833,0.193 0.861,0.099 0.856,-0.122 0.831,-0.193 0.747,-0.33 0.663,-0.411 0.464,-0.536 0.389,-0.559
  Top Layer lines w0.152: 0.156,0.557 ccw(c0.277,0) 0.008,0.502 ccw(c0.277,0) -0.293,0 ccw(c0.277,0) 0.16,-0.558 ; 0.465,-0.557 ccw(c0.343,0) 0.466,0.557
Solderbridge_SHORTED_0.4 [mm]
  round 0.2 smd paste-10: 1(0,0) 2(0.625,0)
  Top Layer region: 0.236,-0.553 0.183,-0.605 0.107,-0.554 -0.097,-0.351 -0.15,-0.292 -0.208,-0.193 -0.236,-0.099 -0.231,0.122 -0.206,0.193 -0.122,0.33 -0.038,0.411 0.054,0.469 0.153,0.556 0.233,0.565
  Top Layer region: 0.389,0.553 0.516,0.512 0.648,0.424 0.721,0.351 0.775,0.292 0.833,0.193 0.861,0.099 0.856,-0.122 0.831,-0.193 0.747,-0.33 0.663,-0.411 0.464,-0.536 0.389,-0.559
  Top Layer lines w0.152: 0.16,-0.558 cw(c0.277,0) 0.156,0.557 ; 0.465,-0.557 ccw(c0.343,0) 0.466,0.557
  Top Layer lines w0.203: 0.676,0 0,0
SON50P200X80_HS-7N [mm] "SON, 6-Leads, Body 2,00x2,00mm, Pitch 0,50mm, Thermal Pad 1,37x0,56mm, IPC Medium Density"
  rect 0.85x0.25 smd: 1(-0.94,0.5) 2(-0.94,0) 3(-0.94,-0.5) 4(0.94,-0.5) 5(0.94,0) 6(0.94,0.5)
  rect 0.56x1.37 smd: 7(0,0)
  silkscreen extent -1.65,-1.2 1.2,1.25, body extent -1.05,-1 1.05,1, height 0.79
SOT-23a [mil] "SOT-23 footprint"
  rect 30x40 smd: 1(0,0) 2(74.8,0) 3(37.4,82.68)
  silkscreen extent -39,-4 94,79, body extent -20,-5 95,87, height 39
TP_SMD_Ø1.0mm [mm]
  round 1 smd paste-5: 1(0,0)
  silkscreen extent -0.7,-0.7 0.7,0.7
XQFN40P180X260X50-16N [mm] "QFN, 16-Leads, Body 1.80x2.60mm, Pitch 0.40mm, IPC Medium Density"
  oval 0.65x0.22 smd paste-0.02 mask+0.062: 1(-0.825,0.6) 2(-0.825,0.2) 3(-0.825,-0.2) 4(-0.825,-0.6) 9(0.825,-0.6) 10(0.825,-0.2) 11(0.825,0.2) 12(0.825,0.6)
  oval 0.22x0.65 smd paste-0.02 mask+0.062: 5(-0.6,-1.225) 6(-0.2,-1.225) 7(0.2,-1.225) 8(0.6,-1.225) 13(0.6,1.225) 14(0.2,1.225) 15(-0.2,1.225) 16(-0.6,1.225)
  silkscreen extent -1.45,-1.4 1,1.4, body extent -0.91,-1.31 0.91,1.31, height 0.55

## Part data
Bat1: library part POLSATBATTERYHOLDER_P, "Polsat Battery holder, Positive pole"
Bat2: library part POLSATBATTERYHOLDER_N, "Polsat Battery holder, Negative pole"
C1 C7: library part C3528-100µF, "Capacitor, Tantalum, ±10%"
C2: library part C0805-22µ, "Capacitor, X5R, ±10%"
C3 C4 C8 C23 C24 C25 C26 C27 C28 C30 C33 C41 C46 C47 C48 C50 C51 C55 C56: library part C0402-100n, "Capacitor, X7R, ±10%"
C5 C9 C10 C11 C12 C17 C49 C53: library part C0402-1µ0, "Capacitor, X5R, ±5%"
C6: library part C0402-33p, "Capacitor, NP0, ±5%"
C13 C14 C16 C18: library part C0402-N.C., "Not mounted"
C15 C32 C35 C42: library part C0402-10n, "Capacitor, X7R, ±10%"
C19 C20 C21 C22: library part C1206-10µ_Tantal, "Capacitor, Tantalum, ±10%"
C29 C36 C43: library part C0805-10µ, "Capacitor, X5R, ±10%"
C31: library part C0402-2µ2, "Capacitor, X5R, ±20%"
C34: library part C0402-470n, "Capacitor, X5R, ±10%"
C37: library part C1206-100u-6.3V, "CAP CER 100UF 6.3V 20% X5R 1206"
C39 C40 C44 C45: library part C0402-15p, "Capacitor, NP0, ±5%"
C52: library part C0402-10µF, "10µF ±20% 10V X5R Ceramic Capacitor -55°C ~ 85°C Surface Mount, MLCC 0402"
C54: library part C0402-4µ7, "Capacitor, X5R, ±20%"
D1: "Diode Schottky Vf=0.38, Vr=40V, If=200mA, Ir=500nA"
FB1: library part FB0402-600R@100MHz-300mA, "Ferrite Bead, 600 Ohm @ 100MHz, 300mA, 600 mOhm Max"
FB2 FB3: library part FB0603-600R@100MHz-500mA, "Ferrite Bead, 600 Ohm @ 100MHz, 500mA, 380 mOhm Max"
Fid1 Fid2: library part Fid-Mark, "Fiducial Mark"
J1: library part SJ-3523-SMT-TR, "CONN AUDIO JACK 3.5MM STEREO SMD"
JP1 JP2: library part Jumper-2.54mm, "Jumper - 2.54mm"
K1 K2 K3 K4 K5 K6 K7 K8 K9 K10 K11 K12 K13 K14 K15 K16 K17 K18 K19 K20 K21 K22 K23 K24 K25 K26 K27 K28 K29 K30 K31 K32 K33 K34 K35 K36 K37 K38 K39 K40 K41 K42 K43 K44 K45 K46 K47: library part KEY_SWITCH_SR3, "Keyboard matrix switch"
LD1: library part IR333C/H2_SIDE, "IR EMITTER, 3MM, 940NM"
LD3 LD4: library part "LG L29K Smartled Green", "LED SMARTLED GREEN 570NM 0603"
LOGO1: "Nordic Logo, medium size"
P1 P4 P8: library part "Pin List 1x8 SMD", "Pin List 1x8, 2.54mm (100mil), SMD"
P2 P9: "Pin List 1x2, 2.54mm (100mil)"
P3: library part "Pin List 1x6 SMD", "Pin List 1x6, 2.54mm (100mil), SMD"
P5: "Pin List 1x4, 2.54mm (100mil)"
P6: library part "Pin List 1x10 SMD", "Pin List 1x10, 2.54mm (100mil), SMD"
P7: library part "Socket 2x3 SMD Bottom", "Socket 2x3, 2.54mm (100mil), SMD"
P10: "Pin List 1x3, 2.54mm (100mil)"
P11: library part VMOB6027D-423G-PAHRAC-00-0, "Omnidirectional Back Electret Condenser Microphone"
P12: library part "Molex 5034800600", "CONN FFC FPC 6POS 0.50MM R/A"
Q1 Q3: "Mosfet FDV303N"
Q2: "Mosfet FDV304P"
Q4 Q5: "BC847C, NPN Silicon transistor"
R1 R25 R31: library part R0402-1M0, "Resistor, ±1%, 0.063W"
R2: library part R0402-220, "Resistor, ±1%, 0.063W"
R3 R12: library part R0402-10R, "Resistor, ±1%, 0.063W"
R4 R14 R16 R18: library part R0402-33R, "Resistor, ±1%, 0.063W"
R5 R8 R11 R13 R17: library part R0402-0R, "Resistor, ±5%, 0.063W"
R6: library part R0402-2k2, "Resistor, ±1%, 0.063W"
R7 R19 R27 R28 R32 R33 R34 R35: library part R0402-N.C., "Not mounted"
R9 R10: library part R0402-4k3, "Resistor, ±1%, 0.063W"
R15: library part R0402-1k0, "Resistor, ±1%, 0.063W"
R20 R21: library part R0402-10k, "Resistor, ±1%, 0.063W"
R22 R24: library part R0402-100, "Resistor, ±1%, 0.063W"
R23: library part R0402-2R2, "Resistor, ±1%, 0.063W"
R26: library part R0402-100k, "Resistor, ±1%, 0.063W"
R29 R30: library part R0402-4k7, "Resistor, ±1%, 0.063W"
R36 R37: library part R0402-820, "Resistor, ±1%, 0.063W"
SB1 SB2 SB3 SB4 SB5 SB9 SB10 SB12 SB14 SB16 SB17 SB20 SB21 SB25 SB26 SB28 SB29 SB32 SB33: library part "Solderbridge Shorted 0.4mm", "Shorted Solderbridge"
SB6 SB7 SB11 SB15 SB18 SB19 SB22 SB23 SB24 SB27 SB30 SB31 SB34 SB35 SB36 SB38: library part "Solderbridge 0.4mm"
SW1 SW2: library part ALPS_SKHUALE010, "ALPS - SKHUALE010 - Tactile Switch, SPNO, SMD, 6.5x6.2x2.5mm"
SW3: library part CJS-1200TA, "SMD slide Switch (ON-ON)"
TP1 TP2: library part TP_SMD_Ø1.0MM, "1.0mm circular SMD testpad"
U1: "High performance, low power and low cost audio ADC. It consists of 2-ch ADC, microphone amplifier and auto level control"
U2: "Gyroscope and Accelerometer, PQFN-16"
U3: "3-axis - ±2g/±4g/±8g/±16g digital output nano accelerometer"
U4 U6: "MEMS audio sensor omnidirectional digital microphone"
U5 U10 U12: library part NX3DV2567GU, "Low-ohmic four-pole double-throw analog switch"
U7: "IC GPIO EXPANDER I2C 16CH 28QFN"
U8: "XLATOR/BUFF/REPEAT/ISOLATR 8UMLPd"
U9: "IC REG MULTI CONFIG 3.3V 6DFN"

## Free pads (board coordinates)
  oval 3.5x6 hole 3 slot 5.5 at 90 deg: 0(223.37,22.025)
  round 3.5 hole 3.5: 1(11.7,19.432) 1(11.7,35.432) 1(84.905,27.45) 1(153.1,27.432)
  round 3.5 hole 3.5 unplated: 1(22.417,27.432)
  round 2.2 hole 2.2: 1(79.3,35.732)
  round 4.2 hole 4.2: 1(155.3,19.932) 1(155.3,34.932)
  round 3.2 hole 3.2: 1(188.21,3.243) 1(189.48,51.503) 1(240.28,8.323) 1(240.28,36.263) 1(264.41,51.503) 1(270.76,3.243)

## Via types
v1: diameter 0.61, hole 0.305, Top Layer to Bottom Layer, tented both sides, 1823 vias
v2: diameter 0.6, hole 0.3, Top Layer to Bottom Layer, tented both sides, 4 vias

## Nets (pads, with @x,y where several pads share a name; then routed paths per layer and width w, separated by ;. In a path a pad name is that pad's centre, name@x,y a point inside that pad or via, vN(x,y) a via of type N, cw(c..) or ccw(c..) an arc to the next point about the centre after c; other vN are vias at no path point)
3V3: C51.2 C54.2 P12.6 R2.2 R29.1 R30.1 R34.1 R35.1 U8.8 U9.3 | length 32.5
  Top Layer w0.254: v1(205.702,21.027) 205.716,21.04 v1(205.716,23.476)
  Bottom Layer w0.254: v1@205.69,23.501 v1(205.716,23.476) ; U8.8@205.702,21.516 v1(205.702,21.027) 205.955,20.774 C51.2@205.955,20.163 206.394,20.163 R29.1@206.827,20.596 ; U9.3@208.027,18.003 206.91,18.003 C54.2@206.812,18.101 206.827,18.115 R29.1@206.827,20.596 ; R2.2@212.1,18.707 211.436,19.371 209.355,19.371 208.648,20.078 P12.6@208.648,20.775 207.752,20.775 207.558,20.582 206.841,20.582 R29.1@206.827,20.596
  Bottom Layer w0.305: v1@205.69,23.501 R30.1@206.829,23.501 208.129,24.801 214.439,24.801 216.691,27.054 R35.1@216.798,27.054 218.539,27.054 220.249,25.344 R34.1@220.667,25.344
A1: LD3.1 SB1.1 | length 76
  Top Layer w0.203: SB1.1@227.622,4.477 227.622,14.86 v1(228.981,16.219) ; v1(283.82,16.219) LD3.1@292.671,16.219
  Bottom Layer w0.203: v1(228.981,16.219) v1(283.82,16.219)
A2: P3.3 U5.16 | length 49.9
  Top Layer w0.203: v1(216.286,38.443) 216.598,38.131 216.598,32.838 219.847,29.589 219.847,13.502 v1(219.826,13.481)
  Top Layer w0.254: v1(230.115,13.492) 230.12,13.487 v1(230.12,6.108)
  Bottom Layer w0.203: v1(216.286,38.443) 216.298,38.455 U5.16@217.711,38.455
  Bottom Layer w0.254: v1(219.826,13.481) 219.842,13.464 219.851,13.472 230.096,13.472 v1(230.115,13.492) ; P3.3@230.12,1.778 P3.3@230.12,4.708 v1(230.12,6.108)
A3: P3.4 U5.5 | length 50.2
  Top Layer w0.203: v1(220.311,39.106) 219.885,38.68 219.885,31.404 221.204,30.085 v1(221.204,15.074)
  Top Layer w0.254: v1(232.649,6.446) v1(232.649,15.056)
  Bottom Layer w0.203: U5.5@220.161,38.455 220.161,38.956 v1(220.311,39.106)
  Bottom Layer w0.254: v1(221.204,15.074) 221.222,15.056 v1(232.649,15.056) ; v1(232.649,6.446) 232.66,6.435 P3.4@232.66,4.708 P3.4@232.66,1.778
A4: SB2.1 U12.7 | length 40.5
  Top Layer w0.203: v1(227.775,32.181) 227.777,32.183 v1(227.777,35.618) ; v1(233.934,32.181) 233.934,8.389 235.211,7.112 235.211,4.652 SB2.1@235.211,4.477
  Bottom Layer w0.203: U12.7@226.941,37.705 227.414,37.705 227.777,37.342 v1(227.777,35.618) ; v1(227.775,32.181) v1(233.934,32.181)
A5: P3.6 U5.12 | length 53.5
  Top Layer w0.203: v1(218.336,36.152) 218.336,31.65 220.396,29.59 220.396,14.507 220.214,14.326 v1(220.396,14.326) ; v1(237.397,14.322) 237.397,7.052 v1(237.739,6.709)
  Bottom Layer w0.203: v1(218.336,36.152) U5.12@218.336,37.03 ; v1(220.396,14.326) 237.393,14.326 v1(237.397,14.322) ; P3.6@237.74,4.708 v1@237.74,6.709
  Bottom Layer w0.254: P3.6@237.74,1.778 P3.6@237.74,4.708
"D0 (RX)": SB33.1 U5.8 U12.3 | length 31.5
  Top Layer w0.203: v1(226.373,40.308) v1(226.373,47.155) ; v1(237.767,47.161) 237.767,48.186 237.768,48.187 SB33.1@237.768,50.257
  Bottom Layer w0.203: U5.8@220.161,37.255 220.74,37.255 221.492,38.007 221.492,39.518 222.288,40.313 226.368,40.313 v1(226.373,40.308) 226.373,39.481 225.915,39.023 225.915,38.748 U12.3@225.916,38.747 ; v1(226.373,47.155) 226.368,47.161 v1(237.767,47.161)
"D1 (TX)": SB3.1 U10.16 | length 16.2
  Top Layer w0.203: SB3.1@235.196,50.257 235.196,49.158 235.756,48.597 235.756,36.785 v1(235.759,36.782)
  Bottom Layer w0.203: U10.16@233.499,37.305 233.959,37.305 234.482,36.782 v1(235.759,36.782)
D2: P4.3 U10.8 | length 16.1
  Top Layer w0.203: v1(230.699,39.575) 230.699,49.155 v1(231.592,50.049)
  Bottom Layer w0.203: v1(230.699,39.575) 230.699,39.291 231.049,38.942 U10.8@231.049,38.505 ; v1(231.592,50.049) 232.65,50.049 P4.3@232.66,50.038
  Bottom Layer w0.305: P4.3@232.66,50.038 P4.3@232.66,52.968
D3: P4.4 U10.12 | length 16.4
  Top Layer w0.203: v1(231.673,49.216) 232.392,49.216 232.874,48.734 v1(232.874,39.926)
  Bottom Layer w0.203: P4.4@230.12,50.038 230.046,49.964 230.862,49.964 231.61,49.216 v1(231.673,49.216) ; U10.12@232.874,38.73 v1(232.874,39.926)
  Bottom Layer w0.305: P4.4@230.12,50.038 P4.4@230.12,52.968
D5: LD4.1 SB4.1 | length 99.7
  Top Layer w0.203: SB4.1@225.044,50.252 225.044,49.516 v1(226.02,48.54) ; v1(236.348,47.863) 236.348,46.839 236.88,46.307 236.88,22.586 236.569,22.275 236.569,20.149 236.572,20.147 236.572,17.509 236.555,17.526 v1(236.55,17.526) ; v1(283.82,17.496) 292.664,17.496 LD4.1@292.671,17.503
  Bottom Layer w0.203: v1(226.02,48.54) 226.041,48.562 235.65,48.562 v1(236.348,47.863) ; v1(236.55,17.526) 282.324,17.526 282.354,17.496 v1(283.82,17.496) v1@283.789,17.526
D6: SB5.1 U10.4 | length 22.7
  Top Layer w0.203: SB5.1@222.5,50.259 222.5,49.432 224.028,47.904 v1(224.028,46.634) ; v1(231.27,46.621) 231.233,46.583 231.233,39.33 230.92,39.018 230.92,37.267 231.674,36.513 v1(231.674,36.485)
  Bottom Layer w0.203: v1(224.028,46.634) 224.028,46.623 224.029,46.621 v1(231.27,46.621) ; v1(231.674,36.485) U10.4@231.674,37.08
